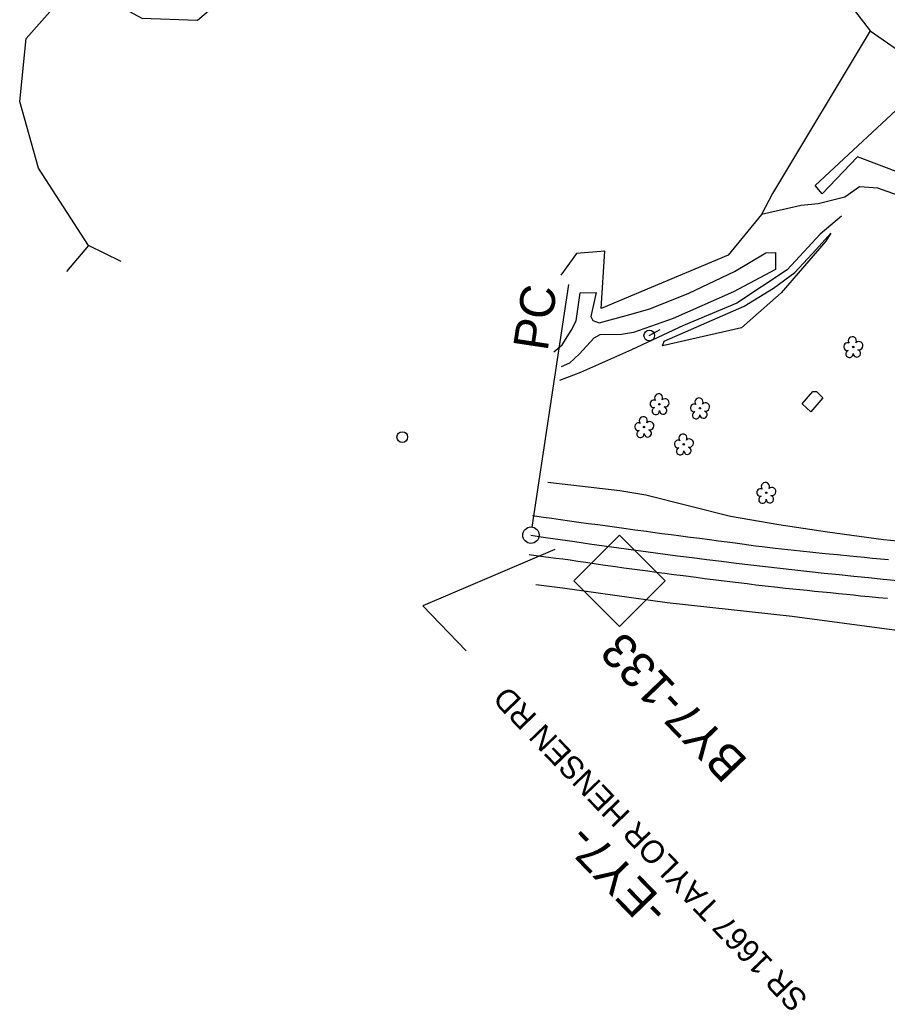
# Model space of a CAD drawing. Extents: x 474972 to 479313, y 498315 to 502691.
# Drawn here: x 475997.6 to 476395.3, y 500515.9 to 500969.8 of the extents above; entities that cross this region are included whole.
import ezdxf

# ---------------------------------------------------------------- set-up
doc = ezdxf.new("R2010")
doc.units = 0
for name, color, linetype in [('CTL Secondary Horizontal and Vertical CELL', 7, 'Continuous'), ('CTL Secondary Horizontal and Vertical Text', 7, 'Continuous'), ('Exist Horizontal Alignment', 7, 'Continuous'), ('Exist Horizontal Alignment Direction Label', 7, 'Continuous'), ('Exist Other Culture Area Outline', 7, 'Continuous'), ('Exist Other Culture Fence Line', 7, 'Continuous'), ('Exist Roads EOP', 7, 'Continuous'), ('Exist Roads EOP Leader', 7, 'Continuous'), ('Exist Roads EOP Text', 7, 'Continuous'), ('Exist Roads Soil', 7, 'Continuous'), ('Exist Utilities Other Pole CELL', 7, 'Continuous'), ('Exist Utilities Power Pole CELL', 7, 'Continuous'), ('Exist Vegetation Hedge Row', 7, 'Continuous'), ('Exist Vegetation Tree CELL', 7, 'Continuous'), ('Exist Vegetation Woods Line', 7, 'Continuous')]:
    doc.layers.add(name, color=color, linetype=linetype)

msp = doc.modelspace()

# ---------------------------------------------------------------- linework, layer by layer
at = {"layer": 'CTL Secondary Horizontal and Vertical CELL'}
msp.add_line((476272.43, 500712.57), (476272.43, 500712.57), dxfattribs=at)
msp.add_lwpolyline([(476251.57, 500712.64), (476272.54, 500733.6), (476293.54, 500712.6), (476272.57, 500691.64)], close=True, dxfattribs=at)
at = {"layer": 'Exist Horizontal Alignment'}
msp.add_line((476232.53, 500737.27), (476249.35, 500848.48), dxfattribs=at)
msp.add_circle((476231.96, 500733.57), 3.75, dxfattribs=at)
for centre, radius, start, end in [((478672.62, 502845.57), 2932.7, 213.99726, 223.91157), ((476696.75, 503806.31), 3107.69, 261.3986, 265.40049)]:
    msp.add_arc(centre, radius, start, end, dxfattribs=at)
at = {"layer": 'Exist Other Culture Area Outline'}
msp.add_lwpolyline([(476356.36, 500793.74), (476361.29, 500799.34), (476362.95, 500799.45), (476365.81, 500796.56), (476360.38, 500790.1)], close=True, dxfattribs=at)
at = {"layer": 'Exist Other Culture Fence Line'}
for points in [[(476374.41, 500879.71), (476364.59, 500871.48), (476349.46, 500855.19), (476326.41, 500839.95), (476301.9, 500829.72), (476278.13, 500818.48), (476254.63, 500808.16), (476245.08, 500804.52)], [(476239.65, 500757.8), (476250.32, 500756.64), (476272.68, 500754.03), (476284.64, 500752.07), (476323.41, 500742.23), (476345.63, 500738.53), (476367.99, 500735.09), (476393.64, 500731.52), (476438.64, 500727.27)], [(476437.8, 500683.85), (476399.76, 500689.93), (476351.74, 500696.3), (476294.41, 500702.48), (476246.36, 500709.31), (476234.18, 500710.79)]]:
    msp.add_lwpolyline(points, dxfattribs=at)
at = {"layer": 'Exist Roads EOP'}
for points in [[(476232.72, 500742.56), (476237.7, 500741.85), (476241.52, 500741.3), (476245.55, 500740.73), (476249.71, 500740.15), (476253.96, 500739.56), (476258.29, 500738.97), (476262.69, 500738.38), (476267.09, 500737.78), (476271.38, 500737.2), (476275.56, 500736.63), (476279.64, 500736.06), (476283.7, 500735.5), (476287.83, 500734.95), (476292.03, 500734.39), (476296.31, 500733.84), (476300.63, 500733.28), (476304.98, 500732.72), (476309.36, 500732.15), (476313.77, 500731.57), (476318.03, 500731.01), (476321.96, 500730.49), (476325.56, 500730.01), (476328.83, 500729.56), (476331.91, 500729.14), (476334.96, 500728.74), (476337.97, 500728.36), (476343.88, 500727.65), (476349.73, 500726.99), (476355.51, 500726.38), (476361.24, 500725.79), (476366.92, 500725.2), (476372.55, 500724.63), (476378.26, 500724.06), (476381.43, 500723.76), (476384.85, 500723.44), (476388.53, 500723.1), (476392.26, 500722.76), (476395.86, 500722.43)], [(476395.53, 500704.48), (476391.35, 500704.85), (476387.1, 500705.26), (476383.14, 500705.66), (476379.83, 500706.01), (476376.64, 500706.35), (476373.04, 500706.73), (476369.29, 500707.11), (476365.6, 500707.48), (476362.03, 500707.82), (476358.63, 500708.15), (476355.32, 500708.47), (476352.04, 500708.79), (476348.67, 500709.15), (476345.1, 500709.55), (476339.31, 500710.22), (476335.15, 500710.71), (476331.07, 500711.2), (476327.11, 500711.69), (476323.22, 500712.15), (476319.38, 500712.61), (476315.5, 500713.08), (476311.58, 500713.59), (476307.66, 500714.11), (476301.71, 500714.91), (476297.55, 500715.46), (476293.4, 500716.01), (476289.45, 500716.53), (476285.64, 500717.03), (476281.91, 500717.52), (476278.22, 500718), (476274.55, 500718.48), (476270.8, 500718.99), (476264.89, 500719.85), (476260.95, 500720.44), (476257.07, 500721.02), (476253.41, 500721.55), (476249.98, 500722.04), (476246.66, 500722.49), (476243.41, 500722.92), (476240.03, 500723.37), (476236.52, 500723.85), (476231.21, 500724.57)]]:
    msp.add_lwpolyline(points, dxfattribs=at)
at = {"layer": 'Exist Roads EOP Leader'}
msp.add_lwpolyline([(476242.87, 500726.95), (476182.4, 500701.11), (476202.24, 500680.5)], dxfattribs=at)
at = {"layer": 'Exist Roads Soil'}
for points in [[(476242.48, 500817.64), (476242.52, 500817.65), (476246.3, 500820.87), (476250.47, 500827.3), (476252.63, 500831.84), (476254.61, 500844.64), (476261.9, 500844.81), (476259.49, 500833.81), (476260.39, 500831.93), (476263.29, 500830.86), (476277.29, 500834.7), (476286.46, 500837.32), (476304.41, 500844.47), (476325.35, 500854.37), (476339.65, 500863), (476344.17, 500863.17)], [(476344.17, 500863.17), (476344.1, 500855.32), (476324.86, 500845.07), (476297.19, 500832.84), (476278.92, 500826.5), (476273.47, 500825.49), (476263.49, 500825.45), (476260.77, 500823.92), (476254.19, 500816.64), (476249.6, 500812.38), (476245.81, 500810.78)]]:
    msp.add_lwpolyline(points, dxfattribs=at)
at = {"layer": 'Exist Utilities Other Pole CELL'}
msp.add_circle((476172.96, 500778.52), 2.46, dxfattribs=at)
at = {"layer": 'Exist Utilities Power Pole CELL'}
for q in [(476291.16, 500827.77), (476286.24, 500825.04)]:
    msp.add_line((476286.24, 500825.04), q, dxfattribs=at)
msp.add_circle((476286.24, 500825.04), 2.45, dxfattribs=at)
at = {"layer": 'Exist Vegetation Hedge Row'}
for points in [[(476387.51, 500964.69), (476406.97, 500951.24), (476447.99, 500907.24), (476466.04, 500880.93)], [(476457.55, 500875.04), (476450.44, 500878.26), (476440.52, 500886.42), (476424.84, 500889.98), (476400, 500889.45), (476391.07, 500892.58), (476382.67, 500893.18), (476375.97, 500888.51), (476363.7, 500885.44), (476355.9, 500884.59), (476337.73, 500880.49)], [(476293, 500822.45), (476329.78, 500838.47), (476343.2, 500846.8), (476352.92, 500853.93), (476362.78, 500864.5), (476369.41, 500872.02), (476367.22, 500868.28), (476346.72, 500844.59), (476328.5, 500828.66), (476292.31, 500820.32), (476293, 500822.45)], [(476029.01, 500866.39), (476018.95, 500854.46)]]:
    msp.add_lwpolyline(points, dxfattribs=at)
at = {"layer": 'Exist Vegetation Tree CELL'}
for p, q in [((476379.74, 500819.81), (476379.74, 500819.81)), ((476290.89, 500793.6), (476290.89, 500793.6)), ((476309.42, 500791.72), (476309.42, 500791.72)), ((476283.87, 500783.12), (476283.87, 500783.12)), ((476302.05, 500775.18), (476302.05, 500775.18)), ((476339.85, 500752.97), (476339.85, 500752.97))]:
    msp.add_line(p, q, dxfattribs=at)
for centre in [(476379.74, 500819.81), (476290.89, 500793.6), (476309.42, 500791.72), (476283.87, 500783.12), (476302.05, 500775.18), (476339.85, 500752.97)]:
    msp.add_circle(centre, 0.326, dxfattribs=at)
for centre, radius, start, end in [((476377.13, 500819.96), 1.73, 62.6636, 279.3457), ((476379.35, 500822.68), 1.86, 330.1651, 219.7134), ((476382.28, 500820.4), 1.9, 257.1011, 134.1999), ((476378.03, 500816.69), 1.69, 111.5671, 6.231), ((476381.41, 500816.91), 1.7, 181.2822, 74.56), ((476288.29, 500793.75), 1.73, 62.6636, 279.3457), ((476290.51, 500796.47), 1.86, 330.1651, 219.7134), ((476293.44, 500794.19), 1.9, 257.1011, 134.1999), ((476309.03, 500794.59), 1.86, 330.1651, 219.7134), ((476289.19, 500790.48), 1.69, 111.5671, 6.231), ((476292.57, 500790.7), 1.7, 181.2822, 74.56), ((476306.81, 500791.87), 1.73, 62.6636, 279.3457), ((476307.71, 500788.6), 1.69, 111.5671, 6.231), ((476311.09, 500788.82), 1.7, 181.2822, 74.56), ((476311.97, 500792.31), 1.9, 257.1011, 134.1999), ((476283.49, 500786), 1.86, 330.1651, 219.7134), ((476286.42, 500783.71), 1.9, 257.1011, 134.1999), ((476281.27, 500783.28), 1.73, 62.6636, 279.3457), ((476282.17, 500780), 1.69, 111.5671, 6.231), ((476285.54, 500780.22), 1.7, 181.2822, 74.56), ((476299.45, 500775.33), 1.73, 62.6636, 279.3457), ((476301.67, 500778.05), 1.86, 330.1651, 219.7134), ((476304.6, 500775.77), 1.9, 257.1011, 134.1999), ((476300.35, 500772.06), 1.69, 111.5671, 6.231), ((476303.73, 500772.28), 1.7, 181.2822, 74.56), ((476337.25, 500753.13), 1.73, 62.6636, 279.3457), ((476339.47, 500755.85), 1.86, 330.1651, 219.7134), ((476342.4, 500753.56), 1.9, 257.1011, 134.1999), ((476338.15, 500749.85), 1.69, 111.5671, 6.231), ((476341.53, 500750.07), 1.7, 181.2822, 74.56)]:
    msp.add_arc(centre, radius, start, end, dxfattribs=at)
at = {"layer": 'Exist Vegetation Woods Line'}
for points in [[(476235.13, 501168.55), (476315.23, 501058.66), (476387.51, 500964.69), (476342.8, 500890.14), (476337.73, 500880.49), (476322.46, 500861.9), (476264.16, 500837.46), (476265.8, 500863.73), (476252.8, 500862.59), (476245.69, 500852.68)], [(476044.03, 500858.95), (476029.01, 500866.39), (476006.19, 500901.77), (475997.56, 500932.3), (476000.53, 500961.18), (476023.24, 500987.02), (476053.59, 500970.56), (476079.11, 500969.64), (476109.77, 500995.85), (476086.02, 501034.28), (476120.28, 501107.83)], [(476362.27, 500893.85), (476408.14, 500936.38), (476423.34, 500917.32), (476399.44, 500900.25), (476381.66, 500906.96), (476365.52, 500889.99), (476362.27, 500893.85)]]:
    msp.add_lwpolyline(points, dxfattribs=at)

# ---------------------------------------------------------------- texts
at = {"layer": 'CTL Secondary Horizontal and Vertical Text'}
msp.add_text('BY7-133', height=16, rotation=133.8723, dxfattribs=at).set_placement((476331.97, 500630.13))
at = {"layer": 'Exist Horizontal Alignment'}
msp.add_text('PC', height=16, rotation=81.3986, dxfattribs=at).set_placement((476239.55, 500817.55))
at = {"layer": 'Exist Horizontal Alignment Direction Label'}
msp.add_text('-EY7-', height=16, rotation=134.0734, dxfattribs=at).set_placement((476296.07, 500563.05))
at = {"layer": 'Exist Roads EOP Text'}
msp.add_text('SR 1667 TAYLOR HENSEN RD', height=10.4, rotation=133.8722, dxfattribs=at).set_placement((476359.5, 500521.39))

doc.saveas('drawing.dxf')
